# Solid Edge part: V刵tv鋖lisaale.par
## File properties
Author: Türk
Template: Iso Part.par
Last saved by: Türk
Revision: 6
Application: Solid Edge
Accuracy: 0,990
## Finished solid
Body 1: solid body, 4 faces, 4 edges, 0 vertices.
  Faces by surface: cylinder 2, plane 2
  Edges by curve: circle 4
Bounding box of the edges (mm): 44.000 x 32.000 x 44.000, from (-22, 0, -22) to (22, 32, 22).
Cylindrical faces by radius (mm): R20 x1, R22 x1
Planar faces by outward normal: +y 1, -y 1
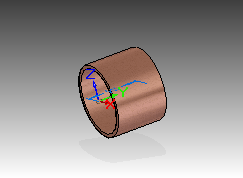
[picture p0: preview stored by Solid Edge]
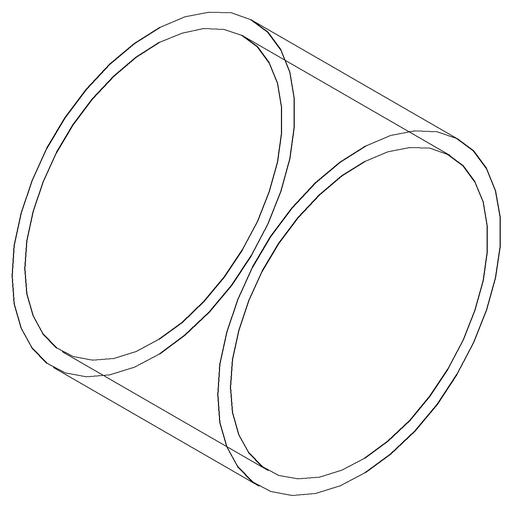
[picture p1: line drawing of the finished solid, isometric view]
